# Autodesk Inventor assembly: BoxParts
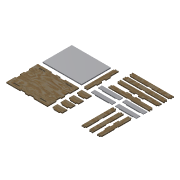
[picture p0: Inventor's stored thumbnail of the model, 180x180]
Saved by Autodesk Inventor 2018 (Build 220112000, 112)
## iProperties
Created: 2018-05
Part Number: BoxParts
Document SubType Name: Assembly
Designer: arivu
Author: arivu
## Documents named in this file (23)
- C:\Users\arivu\Documents\Fabacademy\FinalProject\Boxes\BoxParts.iam
- C:\Users\arivu\Documents\Fabacademy\FinalProject\Boxes\Bottom.ipt
- C:\Users\arivu\Documents\Fabacademy\FinalProject\Boxes\Part1.ipt
- C:\Users\arivu\Documents\Fabacademy\FinalProject\Boxes\Leg.ipt
- C:\Users\arivu\Documents\Fabacademy\FinalProject\Boxes\Part2.ipt
- C:\Users\arivu\Documents\Fabacademy\FinalProject\Boxes\WeightingBottom.ipt
- C:\Users\arivu\Documents\Fabacademy\FinalProject\Boxes\Part3.ipt
- C:\Users\arivu\Documents\Fabacademy\FinalProject\Boxes\TopHolder.ipt
- C:\Users\arivu\Documents\Fabacademy\FinalProject\Boxes\Part4.ipt
- C:\Users\arivu\Documents\Fabacademy\FinalProject\Boxes\BottomEnd.ipt
- C:\Users\arivu\Documents\Fabacademy\FinalProject\Boxes\Part5.ipt
- C:\Users\arivu\Documents\Fabacademy\FinalProject\Boxes\BottomSide.ipt
- C:\Users\arivu\Documents\Fabacademy\FinalProject\Boxes\Part6.ipt
- C:\Users\arivu\Documents\Fabacademy\FinalProject\Boxes\TopSideSupport.ipt
- C:\Users\arivu\Documents\Fabacademy\FinalProject\Boxes\Part7.ipt
- C:\Users\arivu\Documents\Fabacademy\FinalProject\Boxes\BottomEnd2.ipt
- C:\Users\arivu\Documents\Fabacademy\FinalProject\Boxes\Part8.ipt
- C:\Users\arivu\Documents\Fabacademy\FinalProject\Boxes\BottomSide2.ipt
- C:\Users\arivu\Documents\Fabacademy\FinalProject\Boxes\Part9.ipt
- C:\Users\arivu\Documents\Fabacademy\FinalProject\Boxes\TopSide2.ipt
- C:\Users\arivu\Documents\Fabacademy\FinalProject\Boxes\Part10.ipt
- C:\Users\arivu\Documents\Fabacademy\FinalProject\Boxes\TopEnd.ipt
- C:\Users\arivu\Documents\Fabacademy\FinalProject\Boxes\TopEnd2.ipt
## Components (28 placed, 22 different names)
1. Bottom:1 — Flush:7
2. Part1:1
3. Leg:1 — Flush:4
4. Part2:1
5. WeightingBottom:1 — Flush:2
6. Part3:1
7. Leg:2 — Flush:6
8. Leg:3 — Flush:3
9. Leg:4 — Flush:5
10. TopHolder:1 — Flush:8
11. Part4:1
12. TopHolder:2 — Flush:9
13. TopHolder:3 — Flush:11, Flush:12
14. TopHolder:4 — Flush:10
15. BottomEnd:1 — Flush:13
16. Part5:1
17. BottomSide:1 — Flush:15
18. Part6:1
19. TopSideSupport:1 — Flush:17
20. Part7:1
21. BottomEnd2:1 — Flush:18
22. Part8:1
23. BottomSide2:1 — Flush:19
24. Part9:1
25. TopSide2:1 — Flush:20
26. Part10:1
27. TopEnd:1 — Flush:21
28. TopEnd2:1 — Flush:22
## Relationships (19: Flush 19)
- Flush:2: WeightingBottom:1
- Flush:3: Leg:3
- Flush:4: Leg:1
- Flush:5: Leg:4
- Flush:6: Leg:2
- Flush:7: Bottom:1
- Flush:8: TopHolder:1
- Flush:9: TopHolder:2
- Flush:10: TopHolder:4
- Flush:11: TopHolder:3
- Flush:12: TopHolder:3
- Flush:13: BottomEnd:1
- Flush:15: BottomSide:1
- Flush:17: TopSideSupport:1
- Flush:18: BottomEnd2:1
- Flush:19: BottomSide2:1
- Flush:20: TopSide2:1
- Flush:21: TopEnd:1
- Flush:22: TopEnd2:1
